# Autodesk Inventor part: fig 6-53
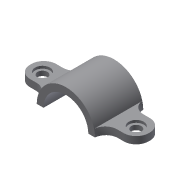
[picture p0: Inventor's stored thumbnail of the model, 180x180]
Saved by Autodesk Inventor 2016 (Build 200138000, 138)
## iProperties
Created: 2004-05
Part Number: fig 6-53
Document SubType Name: Modeling
Designer: CADCIM Technologies
Manufacturer: Standard
Standards Organization: Custom
Density: 1 g/cm^3
Material: Generic
Appearance: Default
Author: CADCIM Technologies
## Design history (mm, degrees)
node "Sketch1"
sketch "Sketch2"
  geometry: L1 (23.378, 0)-(17.996, 0); L2 (-17.996, 0)-(-23.378, 0); A1 r 23.378 centre (0, 0) between (23.378, 0) and (-23.378, 0); A2 r 17.996 centre (0, 0) between (17.996, 0) and (-17.996, 0)
  constraints: 4 end point, 4 point on circle, 2 centre point, 1 collinear, 1 horizontal
extrude "Extrusion1" new body sketch "Sketch2" stored distance "d0" = 38.75; taper "d1" = 0 deg
sketch "Sketch3"
  geometry: L1 (23.378, 0)-(17.996, 0); L2 (-17.996, 0)-(-23.378, 0) reference; L3 (-23.378, 0)-(-47.662, 0); L4 (-47.662, 0)-(-47.662, 5.722); L5 (-47.662, 5.722)-(-22.667, 5.722); A1 r 17.996 centre (0, 0) between (17.996, 0) and (-17.996, 0) reference; A2 r 23.378 centre (0, 0) between (23.378, 0) and (-23.378, 0) reference; 1 further point
  constraints: 10 end point, 5 point on circle, 2 centre point, 1 collinear, 1 horizontal, 1 midpoint, 1 parallel, 1 perpendicular, 3 other
extrude "Extrusion2" join sketch "Sketch3" stored distance "d2" = 21; taper "d3" = 0 deg
fillet "Fillet1" dims "d4" = 10
hole "Hole1" diameter "d7" = 8; stored, may be unused: countersink angle "d11" = 90 deg, drill point angle "d13" = 118 deg; dims "d5" = 10, "d6" = 10, "d8" = 6, "d9" = 12, "d10" = 2, "d12" = 12
fillet "Fillet2" dims "d14" = 9.5
mirror "Mirror1"
body "Solid1"
